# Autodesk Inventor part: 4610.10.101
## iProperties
Shininess: 64.0
Length Units: 11269
Angle Units: 11279
Time Units: 11290
Mass Units: 11283
Length Display Precision: 3
Angle Display Precision: 2
Compacted: True
Part Number: 4610.10.101
Document SubType Name: Modeling
Created: 2004-11
Material: Stahl (hohe Festigk., niedr. Legier.)
Designer: sschwock
Manufacturer: Standard
Standards Organization: Custom
Description: Kugel
Density: 0.0
Volumn: 0.0
Area: 0.0
PropertySet Name: Model Information
Control State: 0
Master: False
Checked Out: False
Author: sschwock
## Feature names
1. Drehung1 [Revolution]
